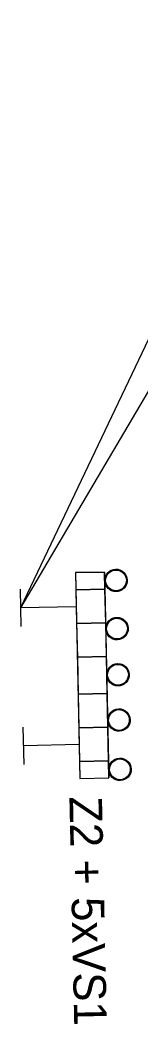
# Model space of a CAD drawing. Extents: x -688893 to -679983, y -1088371 to -1075771.
# Drawn here: x -685510 to -685315, y -1081519 to -1079905 of the extents above; entities that cross this region are included whole.
import ezdxf

# ---------------------------------------------------------------- set-up
doc = ezdxf.new("R2010")
doc.units = 0
doc.layers.add('SDZ', color=7, linetype='Continuous')
doc.layers.add('SDZ plochy', color=7, linetype='Continuous')

msp = doc.modelspace()

# ---------------------------------------------------------------- linework, layer by layer
at = {"layer": 'SDZ'}
for p, q in [((-685420.6, -1080792.9), (-685373.8, -1080791.9)), ((-685420.6, -1080792.9), (-685413.5, -1081124.1)), ((-685373.8, -1080791.9), (-685366.8, -1081123.1)), ((-685510.1, -1080819.6), (-685508.8, -1080879.6)), ((-685420, -1080820.7), (-685373.2, -1080819.7)), ((-685420, -1080820.7), (-685373.2, -1080819.7)), ((-685419.4, -1080847.7), (-685509.4, -1080849.6)), ((-685418.9, -1080874.6), (-685372.1, -1080873.6)), ((-685418.9, -1080874.6), (-685372.1, -1080873.6)), ((-685417.7, -1080928.6), (-685370.9, -1080927.6)), ((-685417.7, -1080928.6), (-685370.9, -1080927.6)), ((-685416.4, -1080988.4), (-685369.7, -1080987.4)), ((-685416.4, -1080988.4), (-685369.7, -1080987.4)), ((-685505.3, -1081041.3), (-685504, -1081101.3)), ((-685415.3, -1081042.4), (-685368.5, -1081041.4)), ((-685415.3, -1081042.4), (-685368.5, -1081041.4)), ((-685414.7, -1081069.4), (-685504.7, -1081071.3)), ((-685414.1, -1081096.4), (-685367.3, -1081095.4)), ((-685414.1, -1081096.4), (-685367.3, -1081095.4)), ((-685413.5, -1081124.1), (-685366.8, -1081123.1))]:
    msp.add_line(p, q, dxfattribs=at)
for points in [[(-685058.5, -1079904.5), (-685509.4, -1080849.6)], [(-685118.1, -1080187.2), (-685509.4, -1080849.6)]]:
    msp.add_lwpolyline(points, dxfattribs=at)
for centre, major_axis in [((-685355.5, -1080805.4), (-2.9, -17.8)), ((-685355.5, -1080805.4), (-2.7, -16.5)), ((-685353.9, -1080882.9), (-2.9, -17.8)), ((-685353.9, -1080882.9), (-2.7, -16.5)), ((-685352.3, -1080957.1), (-2.9, -17.8)), ((-685352.3, -1080957.1), (-2.7, -16.5)), ((-685350.7, -1081029.9), (-2.9, -17.8)), ((-685350.7, -1081029.9), (-2.7, -16.5)), ((-685349.1, -1081109.2), (-2.9, -17.8)), ((-685349.1, -1081109.2), (-2.7, -16.5))]:
    msp.add_ellipse(centre, major_axis=major_axis, ratio=0.999898, dxfattribs=at)
at = {"layer": 'SDZ plochy'}
for p, q in [((-685373.8, -1080791.9), (-685420.6, -1080792.9)), ((-685420.6, -1080792.9), (-685420, -1080820.7)), ((-685373.2, -1080819.7), (-685373.8, -1080791.9)), ((-685373.2, -1080819.7), (-685420, -1080820.7)), ((-685420, -1080820.7), (-685373.2, -1080819.7)), ((-685372.1, -1080873.6), (-685373.2, -1080819.7)), ((-685418.9, -1080874.6), (-685372.1, -1080873.6)), ((-685372.1, -1080873.6), (-685418.9, -1080874.6)), ((-685418.9, -1080874.6), (-685417.7, -1080928.6)), ((-685370.9, -1080927.6), (-685372.1, -1080873.6)), ((-685370.9, -1080927.6), (-685417.7, -1080928.6)), ((-685417.7, -1080928.6), (-685370.9, -1080927.6)), ((-685417.7, -1080928.6), (-685416.4, -1080988.4)), ((-685369.7, -1080987.4), (-685370.9, -1080927.6)), ((-685416.4, -1080988.4), (-685369.7, -1080987.4)), ((-685369.7, -1080987.4), (-685416.4, -1080988.4)), ((-685416.4, -1080988.4), (-685415.3, -1081042.4)), ((-685368.5, -1081041.4), (-685369.7, -1080987.4)), ((-685368.5, -1081041.4), (-685415.3, -1081042.4)), ((-685415.3, -1081042.4), (-685368.5, -1081041.4)), ((-685367.3, -1081095.4), (-685368.5, -1081041.4)), ((-685414.1, -1081096.4), (-685367.3, -1081095.4)), ((-685367.3, -1081095.4), (-685414.1, -1081096.4)), ((-685414.1, -1081096.4), (-685413.5, -1081124.1)), ((-685366.8, -1081123.1), (-685367.3, -1081095.4)), ((-685413.5, -1081124.1), (-685366.8, -1081123.1))]:
    msp.add_line(p, q, dxfattribs=at)
for points in [[(-685420, -1080820.7), (-685419.4, -1080847.7), (-685418.9, -1080874.6)], [(-685415.3, -1081042.4), (-685414.7, -1081069.4), (-685414.1, -1081096.4)]]:
    msp.add_lwpolyline(points, dxfattribs=at)
for centre, radius in [((-685355.5, -1080805.4), 18), ((-685355.5, -1080805.4), 16.7), ((-685355.5, -1080805.4), 16.7), ((-685353.9, -1080882.9), 18), ((-685353.9, -1080882.9), 16.7), ((-685353.9, -1080882.9), 16.7), ((-685352.3, -1080957.1), 18), ((-685352.3, -1080957.1), 16.7), ((-685352.3, -1080957.1), 16.7), ((-685350.7, -1081029.9), 18), ((-685350.7, -1081029.9), 16.7), ((-685350.7, -1081029.9), 16.7), ((-685349.1, -1081109.2), 18), ((-685349.1, -1081109.2), 16.7), ((-685349.1, -1081109.2), 16.7)]:
    msp.add_circle(centre, radius, dxfattribs=at)

# ---------------------------------------------------------------- texts
at = {"layer": 'SDZ'}
msp.add_text('Z2 + 5xVS1', height=52.5, rotation=271.2233, dxfattribs=at).set_placement((-685430.6, -1081153.2))

doc.saveas('drawing.dxf')
